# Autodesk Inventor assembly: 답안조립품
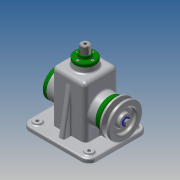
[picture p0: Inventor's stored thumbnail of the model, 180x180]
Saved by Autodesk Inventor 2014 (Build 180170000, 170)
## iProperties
Created: 2015-12
Part Number: 답안조립품
Document SubType Name: Assembly
Designer: Administrator
Author: Administrator
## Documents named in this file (19)
- D:\451225V1018\답안조립품.iam
- D:\451225V1018\본체.ipt
- D:\451225V1018\편심축.ipt
- D:\451225V1018\베어링 15 x 35 x 11.ipt
- D:\451225V1018\멈춤링 15 x 1.ipt
- D:\451225V1018\오일실 15 25 7.ipt
- D:\451225V1018\앞커버.ipt
- D:\451225V1018\키 5 x 5 x 14.ipt
- D:\451225V1018\와셔.ipt
- D:\451225V1018\볼트 M6 x 12.ipt
- D:\451225V1018\V-벨트풀리.ipt
- D:\451225V1018\볼트 M4 x 10.ipt
- D:\451225V1018\뒤커버.ipt
- D:\451225V1018\슬라이드바.ipt
- D:\451225V1018\볼트 M3 x 8.ipt
- D:\451225V1018\상부부시.ipt
- D:\451225V1018\링크.ipt
- D:\451225V1018\고정핀.ipt
- D:\451225V1018\멈춤링 6 x 5.ipt
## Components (15 placed, 5 different names)
1. ISO 4018 M6 x 12:1
2. V-벨트풀리:1
3. 고정핀:1
4. ISO 4762 M4 x 10:1
5. ISO 4762 M4 x 10:2
6. ISO 4762 M4 x 10:3
7. ISO 4762 M4 x 10:4
8. ISO 4762 M4 x 10:5
9. ISO 4762 M4 x 10:6
10. ISO 4762 M4 x 10:7
11. ISO 4762 M4 x 10:8
12. ISO 4762 M3 x 8:1
13. ISO 4762 M3 x 8:2
14. ISO 4762 M3 x 8:3
15. ISO 4762 M3 x 8:4
